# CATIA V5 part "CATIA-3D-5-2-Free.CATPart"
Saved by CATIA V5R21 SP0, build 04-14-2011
Part number: CATIA-3D-5-2-Free
Bounding box of the stored display mesh (mm): x 0 to 135, y -39.5 to 39.5, z 0 to 89
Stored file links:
  C:\Users\Rasoul Mohammadi\Desktop\CATIA-Free\3D\CATIA-3D-5-2-Free.CATPart
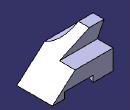
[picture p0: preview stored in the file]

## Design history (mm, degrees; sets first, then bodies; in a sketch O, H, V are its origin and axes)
Body1 (main body)
  Sketch1 on zx-plane, origin (0, 0, 0), H (-1, 0, 0), V (0, 0, 1)
    point P1 (-135, 0)
    line L1 (-135, 0) -> (0, 0)
    line L2 (0, 0) -> (0, 89)
    line L3 (0, 89) -> (-32.6172, 89)
    line L4 (-32.6172, 89) -> (-135, 0)
    length L1 = 135
    length L2 = 89
    angle L4 L1 = 41
    coincidence: P1 H
    horizontal: L1 H, L3 H
    vertical: L2 V
  Pad1: profile Sketch1, direction (0, 1, 0), length 39.5, mirrored extent
  Sketch2 on yz-plane, origin (0, 0, 0), H (0, 1, 0), V (0, 0, 1)
    projected line E1 (-39.5, 89) -> (39.5, 89) from edge [face of Pad1 from Sketch1.L4 | face of Pad1 from Sketch1.L3]
    projected line E2 (19.1214, 89) -> (39.5, 89) from edge [face of Pad1 from Sketch1.L4 | face of Pad1 from Sketch1.L3]
    point P2 (39.5, 89)
    projected line E3 (39.5, 89) -> (39.5, 0) from edge [face of Pad1 from Sketch1.L4 | end face of Pad1]
    projected line E4 (39.5, 89) -> (39.5, 44) from edge [face of Pad1 from Sketch1.L4 | end face of Pad1]
    point P3 (39.5, 89)
    point P5 (39.5, 44)
    line L1 (39.5, 44) -> (4.5, 44)
    line L2 (4.5, 44) -> (19.1214, 89)
    point P7 (19.1214, 89)
    arc A1 centre (-48.5, 97) radius 44 from (-46.8962, 53.0292) to (-4.5313, 95.342) ccw
    point P8 (-48.5, 97)
    reference projected line E5 (-39.5, 0) -> (39.5, 0) from edge [face of Pad1 from Sketch1.L1 | face of Pad1 from Sketch1.L4]
    reference projected line E6 (-39.5, 89) -> (-39.5, 0) from edge [start face of Pad1 | face of Pad1 from Sketch1.L4]
    line L3 (-4.5313, 95.342) -> (-46.8962, 95.342)
    line L4 (-46.8962, 95.342) -> (-46.8962, 53.0292)
    length L1 = 35
    angle L2 L1 = 72
    distance L1 H = 44
    radius A1 = 44
    distance P8 E5 = 97
    distance P8 E6 = 9
    coincidence: P5 E3, P7 E1, P2 P3
    horizontal: L1 H, L3 H
    vertical: L4 V
  Pocket1: profile Sketch2, direction (-1, 0, 0), through (limit type 6)
  Sketch3 on xy-plane, origin (0, 0, 0), H (1, 0, 0), V (0, 1, 0)
    projected line E1 (0, 39.5) -> (84.3838, 39.5) from edge [face of Pocket1 from Sketch2.L1 | end face of Pad1]
    projected line E2 (44.9123, 39.5) -> (84.3838, 39.5) from edge [face of Pocket1 from Sketch2.L1 | end face of Pad1]
    point P2 (84.3838, 39.5)
    projected line E3 (84.3838, 39.5) -> (135, 39.5) from edge [face of Pad1 from Sketch1.L4 | end face of Pad1]
    projected line E4 (84.3838, 39.5) -> (108, 39.5) from edge [face of Pad1 from Sketch1.L4 | end face of Pad1]
    point P3 (84.3838, 39.5)
    projected line E5 (72.9603, -39.5) -> (135, -39.5) from edge [start face of Pad1 | face of Pad1 from Sketch1.L4]
    projected line E6 (72.9603, -39.5) -> (82.3313, -39.5) from edge [start face of Pad1 | face of Pad1 from Sketch1.L4]
    point P5 (72.9603, -39.5)
    projected line E7 (0, -39.5) -> (72.9603, -39.5) from edge [start face of Pad1 | face of Pocket1 from Sketch2.A1]
    projected line E8 (19.2436, -39.5) -> (72.9603, -39.5) from edge [start face of Pad1 | face of Pocket1 from Sketch2.A1]
    point P8 (72.9603, -39.5)
    line L1 (108, 39.5) -> (82.3313, -39.5)
    point P9 (108, 39.5)
    point P10 (82.3313, -39.5)
    reference projected line E9 (135, -39.5) -> (135, 39.5) from edge [face of Pad1 from Sketch1.L1 | face of Pad1 from Sketch1.L4]
    line L2 (44.9123, 39.5) -> (19.2436, -39.5)
    point P11 (44.9123, 39.5)
    point P12 (19.2436, -39.5)
    angle E3 L1 = 72
    distance P9 E9 = 27
    distance L2 L1 = 60
    coincidence: P9 E3, P10 E7, P12 E7, P11 E1, P2 P3, P5 P8
  Pocket2: profile Sketch3, direction (0, 0, 1), length 14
